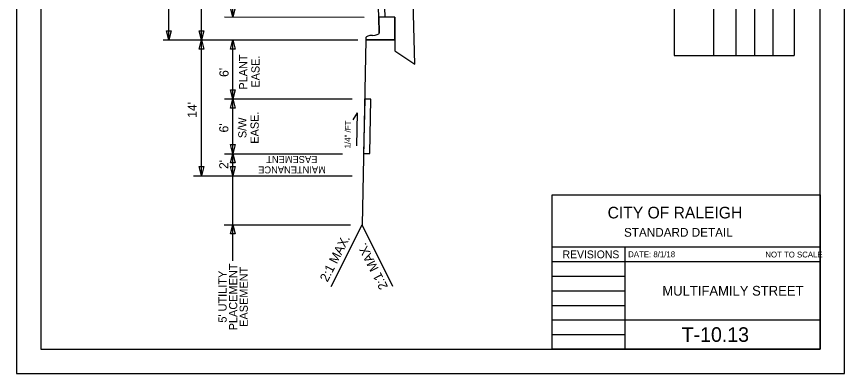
# Model space of a CAD drawing. Extents: x 0 to 8.5, y 0 to 11.
# Drawn here: x 0 to 8.5, y 0 to 3.67 of the extents above; entities that cross this region are included whole.
import ezdxf

# ---------------------------------------------------------------- set-up
doc = ezdxf.new("R2010")
doc.units = 0
for name, color, linetype in [('Old_Level_1', 7, 'Continuous'), ('Old_Level_11', 7, 'Continuous'), ('Old_Level_5', 7, 'Continuous'), ('Prop Shade Light', 7, 'Continuous'), ('SHEET BORDER', 7, 'Continuous'), ('SHEET NOTES', 7, 'Continuous'), ('SHEET TITLE BLOCK LINE', 7, 'Continuous'), ('SHEET TITLE BLOCK TEXT', 7, 'Continuous'), ('SHEET TRIM BORDER', 7, 'Continuous'), ('Typical Pavement Slope Information CELL', 7, 'Continuous')]:
    doc.layers.add(name, color=color, linetype=linetype)

msp = doc.modelspace()

# ---------------------------------------------------------------- linework, layer by layer
at = {"layer": 'Old_Level_1'}
for p, q in [((3.7184, 3.6635), (3.6756, 5.4982)), ((3.7832, 3.6635), (3.7715, 4.1638)), ((3.8834, 3.6635), (3.7181, 3.6635)), ((3.7233, 3.4986), (3.7181, 3.6635)), ((3.8834, 3.6635), (3.8834, 3.4276)), ((3.8834, 3.6635), (3.8834, 3.4276)), ((3.5871, 3.4276), (3.5476, 1.5292)), ((3.5871, 3.4512), (3.5871, 3.4276)), ((3.8834, 3.4276), (3.5871, 3.4276)), ((3.8834, 3.4276), (3.8834, 3.3169)), ((3.8834, 3.3169), (4.0884, 3.1802)), ((3.2306, 0.8951), (3.5476, 1.5292)), ((3.8647, 0.8951), (3.5476, 1.5292))]:
    msp.add_line(p, q, dxfattribs=at)
msp.add_lwpolyline([(4.0884, 3.1802), (4.0263, 5.4981), (4.0884, 7.8163)], dxfattribs=at)
for centre, major_axis, ratio, start_param, end_param in [((3.6509, 3.4983), (-0.0724, 0), 0.32599, 1.618928, 3.151961), ((3.6577, 3.4512), (-0.0708, 0), 0.333333, 4.760521, 6.283197)]:
    msp.add_ellipse(centre, major_axis=major_axis, ratio=ratio, start_param=start_param, end_param=end_param, dxfattribs=at)
at = {"layer": 'Old_Level_11'}
for p, q in [((1.5639, 3.4277), (1.5638, 7.5688)), ((1.8978, 2.0312), (1.8977, 4.4102)), ((2.22, 3.6636), (2.22, 3.8894)), ((2.136, 3.6636), (3.5673, 3.6635)), ((1.5037, 3.4277), (3.5052, 3.4276)), ((2.2201, 2.7282), (2.22, 3.4276)), ((2.1361, 2.821), (3.4459, 2.8209)), ((2.2201, 2.2589), (2.22, 2.7281)), ((2.1361, 2.2589), (3.3461, 2.2589)), ((2.2201, 1.5288), (2.2201, 2.2589)), ((1.8159, 2.0312), (3.4444, 2.0311)), ((2.1326, 1.5288), (3.4292, 1.5288)), ((2.2201, 1.1591), (2.2201, 1.5288))]:
    msp.add_line(p, q, dxfattribs=at)
for points in [[(2.2436, 3.758), (2.22, 3.6636), (2.1964, 3.758)], [(1.5874, 3.522), (1.5638, 3.4277), (1.5402, 3.522)], [(1.9214, 3.522), (1.8978, 3.4276), (1.8742, 3.522)], [(1.8742, 3.3333), (1.8978, 3.4276), (1.9214, 3.3333)], [(2.1964, 3.3332), (2.22, 3.4276), (2.2436, 3.3332)], [(2.2436, 2.9153), (2.22, 2.8209), (2.1965, 2.9153)], [(2.1965, 2.7265), (2.22, 2.8209), (2.2436, 2.7265)], [(2.2437, 2.3533), (2.2201, 2.2589), (2.1965, 2.3533)], [(2.1965, 2.1646), (2.2201, 2.2589), (2.2437, 2.1646)], [(1.9214, 2.1256), (1.8978, 2.0312), (1.8742, 2.1256)], [(2.2437, 2.1255), (2.2201, 2.0311), (2.1965, 2.1255)], [(2.1965, 1.4344), (2.2201, 1.5288), (2.2437, 1.4344)]]:
    msp.add_lwpolyline(points, close=True, dxfattribs=at)
at = {"layer": 'Old_Level_5'}
for points in [[(3.5869, 3.4512), (3.5871, 3.4276), (3.8834, 3.4276), (3.8834, 3.6635), (3.7186, 3.6635)], [(3.7186, 3.6635), (3.7181, 3.6635), (3.7233, 3.4986)], [(3.6544, 3.4748), (3.6543, 3.4748)]]:
    msp.add_lwpolyline(points, dxfattribs=at)
for centre, major_axis, ratio, start_param, end_param in [((3.6509, 3.4983), (-0.0724, 0), 0.32599, 1.618928, 3.151961), ((3.6577, 3.4512), (-0.0708, 0), 0.333333, 4.760521, 6.283197)]:
    msp.add_ellipse(centre, major_axis=major_axis, ratio=ratio, start_param=start_param, end_param=end_param, dxfattribs=at)
at = {"layer": 'Prop Shade Light'}
msp.add_lwpolyline([(3.5744, 2.8179), (3.5628, 2.2591), (3.6267, 2.2591), (3.6375, 2.8179)], close=True, dxfattribs=at)
at = {"layer": 'SHEET BORDER'}
msp.add_lwpolyline([(8.25, 10.75), (0.25, 10.75), (0.25, 0.25), (8.25, 0.25)], close=True, dxfattribs=at)
at = {"layer": 'SHEET NOTES'}
for p, q in [((6.7507, 8.2075), (6.7507, 3.2689)), ((7.1554, 8.2075), (7.1554, 3.2689)), ((7.3863, 8.2075), (7.3863, 3.2689)), ((7.5761, 8.2075), (7.5761, 3.2689)), ((7.7659, 8.2075), (7.7659, 3.2689)), ((7.9825, 8.2075), (7.9825, 3.2689)), ((6.7507, 3.2689), (7.9825, 3.2689))]:
    msp.add_line(p, q, dxfattribs=at)
at = {"layer": 'SHEET TITLE BLOCK LINE'}
for p, q in [((5.5002, 1.2999), (8.25, 1.2999)), ((6.2501, 0.25), (6.2501, 1.2999)), ((5.5002, 1.1499), (8.25, 1.1499)), ((5.5002, 0.9999), (6.2501, 0.9999)), ((5.5002, 0.85), (6.2501, 0.85)), ((5.5002, 0.7), (6.2501, 0.7)), ((5.5002, 0.55), (6.2501, 0.55)), ((6.2501, 0.55), (8.25, 0.55)), ((5.5002, 0.4), (6.2501, 0.4))]:
    msp.add_line(p, q, dxfattribs=at)
msp.add_lwpolyline([(8.25, 0.25), (5.5002, 0.25), (5.5002, 1.8359), (8.25, 1.8359)], close=True, dxfattribs=at)
at = {"layer": 'SHEET TRIM BORDER'}
msp.add_lwpolyline([(8.5, 11), (0, 11), (0, 0), (8.5, 0)], close=True, dxfattribs=at)
at = {"layer": 'Typical Pavement Slope Information CELL'}
for q in [(3.4541, 2.605), (3.4918, 2.3402)]:
    msp.add_line((3.4985, 2.6784), q, dxfattribs=at)

# ---------------------------------------------------------------- texts
at = {"layer": 'Old_Level_11'}
for s, height, rotation, p in [('PLANT', 0.084, 90, (2.3688, 2.9167)), ('EASE.', 0.084, 90, (2.4948, 2.9369)), ("6'", 0.09385, 90.00211, (2.1767, 3.0473)), ("14'", 0.09385, 90, (1.8507, 2.6266)), ('EASE.', 0.084, 90, (2.4862, 2.361)), ("6'", 0.09385, 90.00211, (2.1748, 2.4765)), ('S/W', 0.084, 90, (2.3602, 2.4186)), ('EASEMENT', 0.0714, 180, (3.0887, 2.2348)), ("2'", 0.09385, 90.00211, (2.1748, 2.1011)), ('MAINTENANCE', 0.0714, 180, (3.1757, 2.1277)), ('2:1 MAX.', 0.09385, 62.953, (3.1921, 0.9331)), ('2:1 MAX.', 0.09385, 117.047, (3.8158, 0.8908)), ('PLACEMENT', 0.084, 90, (2.2656, 0.443)), ("5' UTILITY", 0.084, 90, (2.1569, 0.5224)), ('EASEMENT', 0.084, 90, (2.3743, 0.4788))]:
    msp.add_text(s, height=height, rotation=rotation, dxfattribs=at).set_placement(p)
at = {"layer": 'SHEET TITLE BLOCK TEXT'}
for s, height, p in [('CITY OF RALEIGH', 0.12, (6.0686, 1.5932)), ('STANDARD DETAIL', 0.09, (6.2364, 1.4053)), ('REVISIONS', 0.08, (5.6059, 1.184)), ('DATE: 8/1/18', 0.06, (6.2796, 1.195)), ('NOT TO SCALE', 0.06, (7.6877, 1.1922)), ('MULTIFAMILY STREET', 0.100002, (6.6305, 0.8)), ('T-10.13', 0.15, (6.8289, 0.325))]:
    msp.add_text(s, height=height, dxfattribs=at).set_placement(p)
at = {"layer": 'Typical Pavement Slope Information CELL'}
msp.add_text('1/4" /FT', height=0.06078, rotation=88.85215, dxfattribs=at).set_placement((3.428, 2.3122))

doc.saveas('drawing.dxf')
